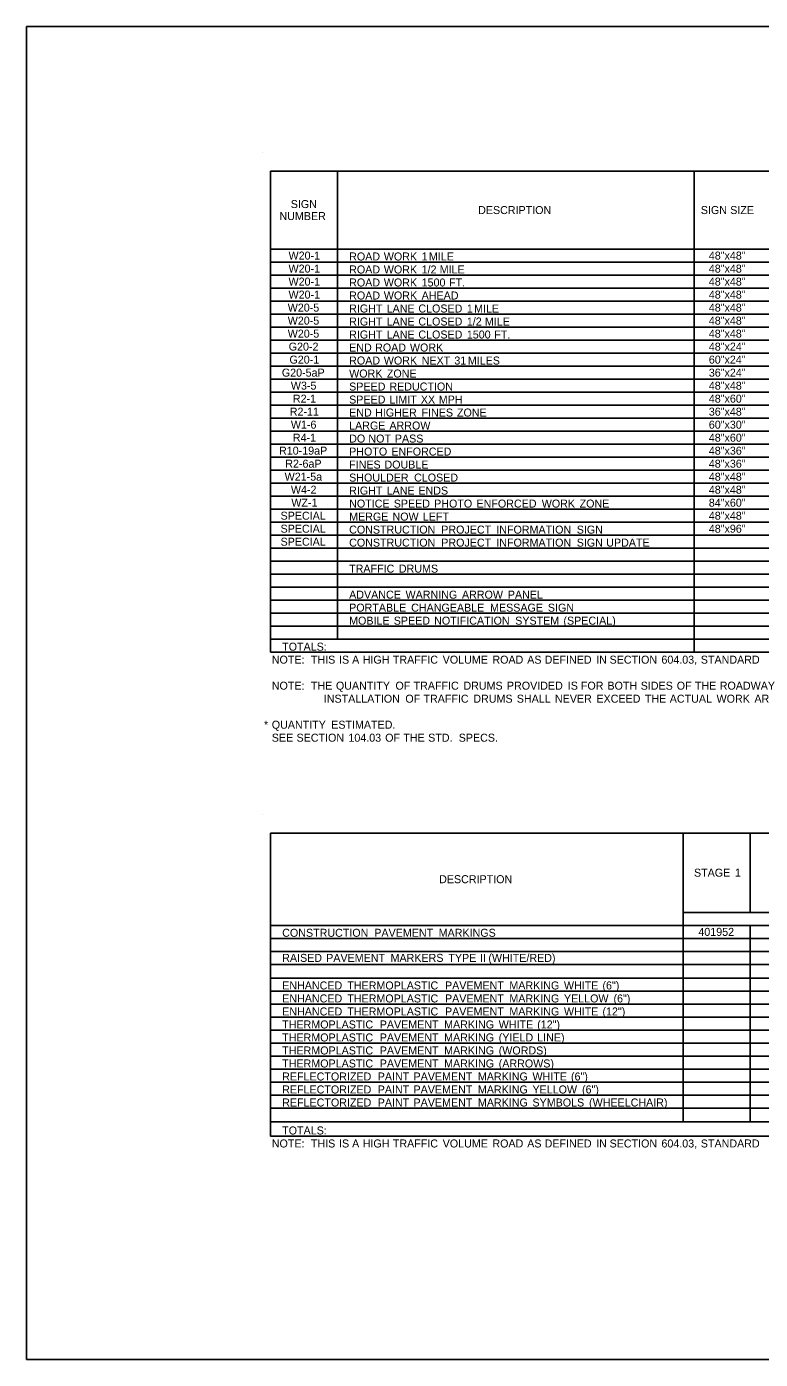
# Model space of a CAD drawing. Extents: x 2261867 to 2275370, y -3124789 to -3122260.
# Drawn here: x 2261867 to 2262418, y -3124789 to -3123790 of the extents above; entities that cross this region are included whole.
import ezdxf

# ---------------------------------------------------------------- set-up
doc = ezdxf.new("R2010")
doc.units = 0
for name, color, linetype in [('Default', 7, 'Continuous'), ('DSN_DRFT_DNC', 7, 'Continuous'), ('DSN_DRFT_Named-Boundary', 7, 'Continuous')]:
    doc.layers.add(name, color=color, linetype=linetype)

msp = doc.modelspace()

# ---------------------------------------------------------------- linework, layer by layer
at = {"layer": 'Default'}
for p, q in [((2262050.38, -3123897.93), (2263056.58, -3123897.93)), ((2262050.38, -3124258.68), (2262050.38, -3123897.93)), ((2262050.38, -3124258.68), (2262050.38, -3123897.93)), ((2262100.59, -3124248.93), (2262100.59, -3123897.93)), ((2262368.23, -3124248.93), (2262368.23, -3123897.93)), ((2262050.38, -3123956.43), (2263056.58, -3123956.43)), ((2262100.59, -3123956.43), (2262368.23, -3123956.43)), ((2262100.59, -3124248.93), (2262100.59, -3123956.43)), ((2262368.23, -3123956.43), (2262569.08, -3123956.43)), ((2262368.23, -3124258.68), (2262368.23, -3123956.43)), ((2262050.38, -3123966.18), (2263056.58, -3123966.18)), ((2262050.38, -3123975.93), (2263056.58, -3123975.93)), ((2262050.38, -3123985.68), (2263056.58, -3123985.68)), ((2262050.38, -3123995.43), (2263056.58, -3123995.43)), ((2262050.38, -3124005.18), (2263056.58, -3124005.18)), ((2262050.38, -3124014.93), (2263056.58, -3124014.93)), ((2262050.38, -3124024.68), (2263056.58, -3124024.68)), ((2262050.38, -3124034.43), (2263056.58, -3124034.43)), ((2262050.38, -3124044.18), (2263056.58, -3124044.18)), ((2262050.38, -3124053.93), (2263056.58, -3124053.93)), ((2262050.38, -3124063.68), (2263056.58, -3124063.68)), ((2262050.38, -3124073.43), (2263056.58, -3124073.43)), ((2262050.38, -3124083.18), (2263056.58, -3124083.18)), ((2262050.38, -3124092.93), (2263056.58, -3124092.93)), ((2262050.38, -3124102.68), (2263056.58, -3124102.68)), ((2262050.38, -3124112.43), (2263056.58, -3124112.43)), ((2262050.38, -3124122.18), (2263056.58, -3124122.18)), ((2262050.38, -3124131.93), (2263056.58, -3124131.93)), ((2262050.38, -3124141.68), (2263056.58, -3124141.68)), ((2262050.38, -3124151.43), (2263056.58, -3124151.43)), ((2262050.38, -3124161.18), (2263056.58, -3124161.18)), ((2262050.38, -3124170.93), (2263056.58, -3124170.93)), ((2262050.38, -3124180.68), (2263056.58, -3124180.68)), ((2262050.38, -3124190.43), (2263056.58, -3124190.43)), ((2262050.38, -3124200.18), (2263056.58, -3124200.18)), ((2262050.38, -3124209.93), (2263056.58, -3124209.93)), ((2262050.38, -3124219.68), (2263056.58, -3124219.68)), ((2262050.38, -3124229.43), (2263056.58, -3124229.43)), ((2262050.38, -3124239.18), (2263056.58, -3124239.18)), ((2262050.38, -3124248.93), (2262368.23, -3124248.93)), ((2262050.38, -3124248.93), (2263056.58, -3124248.93)), ((2262368.23, -3124258.68), (2262368.23, -3124248.93)), ((2262050.38, -3124258.68), (2263056.58, -3124258.68)), ((2262044.53, -3124380.54), (2262044.53, -3124380.54)), ((2262050.38, -3124394.19), (2263251.58, -3124394.19)), ((2262050.38, -3124621.37), (2262050.38, -3124394.19)), ((2262050.38, -3124621.37), (2262050.38, -3124394.19)), ((2262359.94, -3124610.64), (2262359.94, -3124394.19)), ((2262410.15, -3124453.67), (2262410.15, -3124394.19)), ((2262359.94, -3124453.67), (2263251.58, -3124453.67)), ((2262050.38, -3124463.42), (2263251.58, -3124463.42)), ((2262359.94, -3124610.64), (2262359.94, -3124463.42)), ((2262410.15, -3124610.64), (2262410.15, -3124463.42)), ((2262410.15, -3124610.64), (2262410.15, -3124463.42)), ((2262050.38, -3124473.17), (2263251.58, -3124473.17)), ((2262050.38, -3124482.92), (2263251.58, -3124482.92)), ((2262050.38, -3124492.67), (2263251.58, -3124492.67)), ((2262050.38, -3124502.9), (2263251.58, -3124502.9)), ((2262050.38, -3124512.65), (2263251.58, -3124512.65)), ((2262050.38, -3124522.4), (2263251.58, -3124522.4)), ((2262050.38, -3124532.15), (2263251.58, -3124532.15)), ((2262050.38, -3124541.9), (2263251.58, -3124541.9)), ((2262050.38, -3124551.65), (2263251.58, -3124551.65)), ((2262050.38, -3124561.4), (2263251.58, -3124561.4)), ((2262050.38, -3124571.15), (2263251.58, -3124571.15)), ((2262050.38, -3124580.9), (2263251.58, -3124580.9)), ((2262050.38, -3124590.65), (2263251.58, -3124590.65)), ((2262050.38, -3124600.4), (2263251.58, -3124600.4)), ((2262050.38, -3124610.64), (2263251.58, -3124610.64)), ((2262050.38, -3124621.37), (2263251.58, -3124621.37))]:
    msp.add_line(p, q, dxfattribs=at)
at = {"layer": 'DSN_DRFT_DNC'}
msp.add_line((2262044.53, -3123884.28), (2262044.53, -3123884.28), dxfattribs=at)
at = {"layer": 'DSN_DRFT_Named-Boundary'}
msp.add_lwpolyline([(2261867.48, -3124788.75), (2263517.48, -3124788.75), (2263517.48, -3123789.69), (2261867.48, -3123789.69)], close=True, dxfattribs=at)

# ---------------------------------------------------------------- texts
at = {"layer": 'Default'}
for s, p in [('SIGN', (2262065.57, -3123925.68)), ('NUMBER', (2262057.11, -3123934.68)), ('DESCRIPTION', (2262206.1, -3123930.18)), ('SIGN', (2262373.15, -3123930.18)), (' SIZE', (2262392.97, -3123930.18)), ('W20-1', (2262063.91, -3123964.3)), ('ROAD', (2262109.37, -3123964.98)), (' WORK', (2262133.14, -3123964.98)), (' 1', (2262161.53, -3123964.98)), (' MILE', (2262166.98, -3123964.98)), ('48"x48"', (2262379.14, -3123964.3)), ('W20-1', (2262063.91, -3123974.05)), ('ROAD', (2262109.37, -3123974.73)), (' WORK', (2262133.14, -3123974.73)), (' 1/2', (2262161.53, -3123974.73)), (' MILE', (2262175.06, -3123974.73)), ('48"x48"', (2262379.14, -3123974.05)), ('W20-1', (2262063.91, -3123983.8)), ('ROAD', (2262109.37, -3123984.48)), (' WORK', (2262133.14, -3123984.48)), (' 1500', (2262161.53, -3123984.48)), (' FT.', (2262182.1, -3123984.48)), ('48"x48"', (2262379.14, -3123983.8)), ('W20-1', (2262063.91, -3123993.55)), ('ROAD', (2262109.37, -3123994.23)), (' WORK', (2262133.14, -3123994.23)), (' AHEAD', (2262161.53, -3123994.23)), ('48"x48"', (2262379.14, -3123993.55)), ('W20-5', (2262063.31, -3124003.3)), ('RIGHT', (2262109.37, -3124003.98)), (' LANE', (2262135.28, -3124003.98)), (' CLOSED', (2262159.06, -3124003.98)), (' 1', (2262195.41, -3124003.98)), (' MILE', (2262200.86, -3124003.98)), ('48"x48"', (2262379.14, -3124003.3)), ('W20-5', (2262063.31, -3124013.05)), ('RIGHT', (2262109.37, -3124013.73)), (' LANE', (2262135.28, -3124013.73)), (' CLOSED', (2262159.06, -3124013.73)), (' 1/2', (2262195.41, -3124013.73)), (' MILE', (2262208.95, -3124013.73)), ('48"x48"', (2262379.14, -3124013.05)), ('W20-5', (2262063.31, -3124022.8)), ('RIGHT', (2262109.37, -3124023.48)), (' LANE', (2262135.28, -3124023.48)), (' CLOSED', (2262159.06, -3124023.48)), (' 1500', (2262195.41, -3124023.48)), (' FT.', (2262215.98, -3124023.48)), ('48"x48"', (2262379.14, -3124022.8)), ('G20-2', (2262064.06, -3124032.55)), ('END', (2262109.37, -3124033.23)), (' ROAD', (2262126.62, -3124033.23)), (' WORK', (2262152.72, -3124033.23)), ('48"x24"', (2262379.14, -3124032.55)), ('G20-1', (2262064.61, -3124042.3)), ('ROAD', (2262109.37, -3124042.98)), (' WORK', (2262133.14, -3124042.98)), (' NEXT', (2262161.53, -3124042.98)), (' 31', (2262186.05, -3124042.98)), (' MILES', (2262196.16, -3124042.98)), ('60"x24"', (2262379.14, -3124042.3)), ('G20-5aP', (2262058.9, -3124052.05)), ('WORK', (2262109.37, -3124052.73)), (' ZONE', (2262135.43, -3124052.73)), ('36"x24"', (2262379.14, -3124052.05)), ('W3-5', (2262065.64, -3124061.8)), ('SPEED', (2262109.37, -3124062.48)), (' REDUCTION', (2262137.34, -3124062.48)), ('48"x48"', (2262379.14, -3124061.8)), ('R2-1', (2262067.17, -3124071.55)), ('SPEED', (2262109.37, -3124072.23)), (' LIMIT', (2262137.34, -3124072.23)), (' XX', (2262160.92, -3124072.23)), (' MPH', (2262174.38, -3124072.23)), ('48"x60"', (2262379.14, -3124071.55)), ('R2-11', (2262064.84, -3124081.3)), ('END', (2262109.37, -3124081.98)), (' HIGHER', (2262126.62, -3124081.98)), (' FINES', (2262161.44, -3124081.98)), (' ZONE', (2262188.02, -3124081.98)), ('36"x48"', (2262379.14, -3124081.3)), ('W1-6', (2262065.66, -3124091.05)), ('LARGE', (2262109.37, -3124091.73)), (' ARROW', (2262137.34, -3124091.73)), ('60"x30"', (2262379.14, -3124091.05)), ('R4-1', (2262067.17, -3124100.8)), ('DO', (2262109.37, -3124101.48)), (' NOT', (2262121.57, -3124101.48)), (' PASS', (2262141.42, -3124101.48)), ('48"x60"', (2262379.14, -3124100.8)), ('R10-19aP', (2262056.8, -3124110.55)), ('PHOTO', (2262109.37, -3124111.23)), (' ENFORCED', (2262138.8, -3124111.23)), ('48"x36"', (2262379.14, -3124110.55)), ('R2-6aP', (2262061.46, -3124120.3)), ('FINES', (2262109.37, -3124120.98)), (' DOUBLE', (2262133.62, -3124120.98)), ('48"x36"', (2262379.14, -3124120.3)), ('W21-5a', (2262060.99, -3124130.05)), ('SHOULDER', (2262109.37, -3124130.73)), (' CLOSED', (2262155.84, -3124130.73)), ('48"x48"', (2262379.14, -3124130.05)), ('W4-2', (2262065.7, -3124139.8)), ('RIGHT', (2262109.37, -3124140.48)), (' LANE', (2262135.28, -3124140.48)), (' ENDS', (2262159.06, -3124140.48)), ('48"x48"', (2262379.14, -3124139.8)), ('WZ-1', (2262066.01, -3124149.55)), ('NOTICE', (2262109.37, -3124150.23)), (' SPEED', (2262140.59, -3124150.23)), (' PHOTO', (2262170.9, -3124150.23)), (' ENFORCED', (2262202.66, -3124150.23)), (' WORK', (2262251.59, -3124150.23)), (' ZONE', (2262279.98, -3124150.23)), ('84"x60"', (2262379.14, -3124149.55)), ('SPECIAL', (2262057.93, -3124159.3)), ('MERGE', (2262109.37, -3124159.98)), (' NOW', (2262139.66, -3124159.98)), (' LEFT', (2262162.38, -3124159.98)), ('48"x48"', (2262379.14, -3124159.3)), ('SPECIAL', (2262057.93, -3124169.05)), ('CONSTRUCTION', (2262109.37, -3124169.73)), (' PROJECT', (2262176.22, -3124169.73)), (' INFORMATION', (2262217.51, -3124169.73)), (' SIGN', (2262277.83, -3124169.73)), ('48"x96"', (2262379.14, -3124169.05)), ('SPECIAL', (2262057.93, -3124178.8)), ('CONSTRUCTION', (2262109.37, -3124179.48)), (' PROJECT', (2262176.22, -3124179.48)), (' INFORMATION', (2262217.51, -3124179.48)), (' SIGN', (2262277.83, -3124179.48)), (' UPDATE', (2262299.97, -3124179.48)), ('TRAFFIC', (2262109.37, -3124198.98)), (' DRUMS', (2262144.43, -3124198.98)), ('ADVANCE', (2262109.37, -3124218.48)), (' WARNING', (2262149.45, -3124218.48)), (' ARROW', (2262191.77, -3124218.48)), (' PANEL', (2262226.14, -3124218.48)), ('PORTABLE', (2262109.37, -3124228.23)), ('MOBILE', (2262109.37, -3124237.98)), (' SPEED', (2262140.6, -3124237.98)), (' CHANGEABLE', (2262153.65, -3124228.23)), (' NOTIFICATION', (2262170.9, -3124237.98)), (' MESSAGE', (2262212.84, -3124228.23)), (' SYSTEM', (2262231.69, -3124237.98)), (' SIGN', (2262256.19, -3124228.23)), (' (SPECIAL)', (2262267.87, -3124237.98)), ('TOTALS:', (2262059.15, -3124257.48)), ('NOTE:', (2262051.35, -3124267.23)), ('  THIS', (2262076.24, -3124267.23)), (' IS', (2262099.55, -3124267.23)), (' A', (2262109.36, -3124267.23)), (' HIGH', (2262117.3, -3124267.23)), (' TRAFFIC', (2262139.91, -3124267.23)), (' VOLUME', (2262177.3, -3124267.23)), (' ROAD', (2262214.58, -3124267.23)), (' AS', (2262240.69, -3124267.23)), (' DEFINED', (2262253.76, -3124267.23)), (' IN', (2262292.44, -3124267.23)), (' SECTION', (2262302.47, -3124267.23)), (' 604.03,', (2262341.37, -3124267.23)), (' STANDARD', (2262370.91, -3124267.23)), ('NOTE:', (2262051.35, -3124286.73)), ('  THE', (2262076.24, -3124286.73)), (' QUANTITY', (2262097.22, -3124286.73)), (' OF', (2262141.87, -3124286.73)), (' TRAFFIC', (2262155.46, -3124286.73)), (' DRUMS', (2262192.85, -3124286.73)), (' PROVIDED', (2262225.48, -3124286.73)), (' IS', (2262271.15, -3124286.73)), (' FOR', (2262280.96, -3124286.73)), (' BOTH', (2262300.87, -3124286.73)), (' SIDES', (2262325.81, -3124286.73)), (' OF', (2262352.86, -3124286.73)), (' THE', (2262366.45, -3124286.73)), (' ROADWAY', (2262385.1, -3124286.73)), ('INSTALLATION', (2262090.35, -3124296.48)), (' OF', (2262149.3, -3124296.48)), (' TRAFFIC', (2262162.88, -3124296.48)), (' DRUMS', (2262200.27, -3124296.48)), (' SHALL', (2262232.9, -3124296.48)), (' NEVER', (2262261.5, -3124296.48)), (' EXCEED', (2262292.6, -3124296.48)), (' THE', (2262328.96, -3124296.48)), (' ACTUAL', (2262347.61, -3124296.48)), (' WORK', (2262382.72, -3124296.48)), (' AREA', (2262411.11, -3124296.48)), ('*', (2262045.5, -3124315.98)), ('QUANTITY', (2262051.35, -3124315.98)), (' ESTIMATED.', (2262093.68, -3124315.98)), ('SEE', (2262051.35, -3124325.73)), (' SECTION', (2262067.68, -3124325.73)), (' 104.03', (2262106.59, -3124325.73)), (' OF', (2262134.17, -3124325.73)), (' THE', (2262147.76, -3124325.73)), (' STD.', (2262166.41, -3124325.73)), ('  SPECS.', (2262187.1, -3124325.73)), ('STAGE', (2262368, -3124426.93)), (' 1', (2262396.47, -3124426.93)), ('DESCRIPTION', (2262176.85, -3124431.8)), ('CONSTRUCTION', (2262059.15, -3124471.97)), (' PAVEMENT', (2262126, -3124471.97)), (' MARKINGS', (2262174.29, -3124471.97)), ('401952', (2262371.29, -3124471.29)), ('RAISED', (2262059.15, -3124490.79)), (' PAVEMENT', (2262089.92, -3124490.79)), (' MARKERS', (2262138.21, -3124490.79)), (' TYPE', (2262181.56, -3124490.79)), (' II', (2262205.34, -3124490.79)), (' (WHITE/RED)', (2262211.57, -3124490.79)), ('ENHANCED', (2262059.15, -3124511.45)), (' THERMOPLASTIC', (2262105.76, -3124511.45)), (' PAVEMENT', (2262179.03, -3124511.45)), (' MARKING', (2262227.31, -3124511.45)), (' WHITE', (2262268.24, -3124511.45)), (' (6")', (2262297.13, -3124511.45)), ('ENHANCED', (2262059.15, -3124521.2)), (' THERMOPLASTIC', (2262105.76, -3124521.2)), (' PAVEMENT', (2262179.03, -3124521.2)), (' MARKING', (2262227.31, -3124521.2)), (' YELLOW', (2262268.24, -3124521.2)), (' (6")', (2262305.41, -3124521.2)), ('ENHANCED', (2262059.15, -3124530.95)), (' THERMOPLASTIC', (2262105.76, -3124530.95)), (' PAVEMENT', (2262179.03, -3124530.95)), (' MARKING', (2262227.31, -3124530.95)), (' WHITE', (2262268.24, -3124530.95)), (' (12")', (2262297.13, -3124530.95)), ('THERMOPLASTIC', (2262059.15, -3124540.7)), (' PAVEMENT', (2262130.09, -3124540.7)), (' MARKING', (2262178.38, -3124540.7)), (' WHITE', (2262219.31, -3124540.7)), (' (12")', (2262248.19, -3124540.7)), ('THERMOPLASTIC', (2262059.15, -3124550.45)), (' PAVEMENT', (2262130.09, -3124550.45)), (' MARKING', (2262178.38, -3124550.45)), (' (YIELD', (2262219.31, -3124550.45)), (' LINE)', (2262248.2, -3124550.45)), ('THERMOPLASTIC', (2262059.15, -3124560.2)), (' PAVEMENT', (2262130.09, -3124560.2)), (' MARKING', (2262178.38, -3124560.2)), (' (WORDS)', (2262219.31, -3124560.2)), ('THERMOPLASTIC', (2262059.15, -3124569.95)), (' PAVEMENT', (2262130.09, -3124569.95)), (' MARKING', (2262178.38, -3124569.95)), (' (ARROWS)', (2262219.31, -3124569.95)), ('REFLECTORIZED', (2262059.15, -3124579.7)), (' PAINT', (2262128.58, -3124579.7)), (' PAVEMENT', (2262155.43, -3124579.7)), (' MARKING', (2262203.71, -3124579.7)), (' WHITE', (2262244.64, -3124579.7)), (' (6")', (2262273.53, -3124579.7)), ('REFLECTORIZED', (2262059.15, -3124589.45)), (' PAINT', (2262128.58, -3124589.45)), (' PAVEMENT', (2262155.43, -3124589.45)), (' MARKING', (2262203.71, -3124589.45)), (' YELLOW', (2262244.64, -3124589.45)), (' (6")', (2262281.81, -3124589.45)), ('REFLECTORIZED', (2262059.15, -3124599.2)), (' PAINT', (2262128.58, -3124599.2)), (' PAVEMENT', (2262155.43, -3124599.2)), (' MARKING', (2262203.71, -3124599.2)), (' SYMBOLS', (2262244.64, -3124599.2)), (' (WHEELCHAIR)', (2262287.07, -3124599.2)), ('TOTALS:', (2262059.15, -3124620.17)), ('NOTE:', (2262051.35, -3124629.92)), ('  THIS', (2262076.24, -3124629.92)), (' IS', (2262099.55, -3124629.92)), (' A', (2262109.36, -3124629.92)), (' HIGH', (2262117.3, -3124629.92)), (' TRAFFIC', (2262139.91, -3124629.92)), (' VOLUME', (2262177.3, -3124629.92)), (' ROAD', (2262214.58, -3124629.92)), (' AS', (2262240.69, -3124629.92)), (' DEFINED', (2262253.76, -3124629.92)), (' IN', (2262292.44, -3124629.92)), (' SECTION', (2262302.47, -3124629.92)), (' 604.03,', (2262341.37, -3124629.92)), (' STANDARD', (2262370.91, -3124629.92))]:
    msp.add_text(s, height=6, dxfattribs=at).set_placement(p)

doc.saveas('drawing.dxf')
